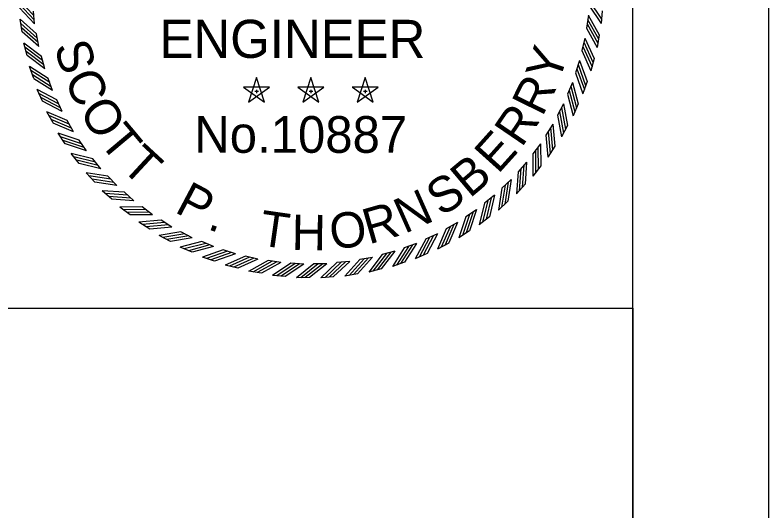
# Model space of a CAD drawing. Extents: x 0 to 1228740, y 0 to 152440.
# Drawn here: x 30.801 to 34, y 16.545 to 18.649 of the extents above; entities that cross this region are included whole.
import ezdxf

# ---------------------------------------------------------------- set-up
doc = ezdxf.new("R2010")
doc.units = 0
for name, color, linetype in [('R_Border', 7, 'Continuous'), ('R_No Plot', 7, 'Continuous'), ('STAMP_PP', 7, 'Continuous')]:
    doc.layers.add(name, color=color, linetype=linetype)

msp = doc.modelspace()

# ---------------------------------------------------------------- linework, layer by layer
at = {"layer": 'R_Border'}
msp.add_line((33.4231, 0.5768), (33.4231, 21.4232), dxfattribs=at)
msp.add_lwpolyline([(34, 22), (0, 22), (0, 0), (34, 0)], close=True, dxfattribs=at)
at = {"layer": 'R_No Plot'}
for points in [[(33.4231, 17.4052), (33.4231, 10.8708), (1.516, 10.8708), (1.516, 21.4232), (25.1971, 21.4232), (25.1971, 20.4352), (28.7491, 20.4352), (28.7491, 20.0782), (29.1131, 20.0782), (29.1131, 20.1432), (30.6665, 20.1432)], [(33.4231, 17.4052), (33.4231, 0.6568), (1.516, 0.6568), (1.516, 21.4232), (25.1971, 21.4232), (25.1971, 20.4352), (28.7491, 20.4352), (28.7491, 20.0782), (29.1131, 20.0782), (29.1131, 20.1432), (30.6665, 20.1432)], [(30.6665, 20.1432), (30.6665, 17.4052), (33.4231, 17.4052)], [(30.6665, 20.1432), (30.6665, 17.4052), (33.4231, 17.4052)]]:
    msp.add_lwpolyline(points, dxfattribs=at)
at = {"layer": 'STAMP_PP'}
for p, q in [((30.8837, 18.6117), (30.8787, 18.666)), ((33.2925, 18.6677), (33.2885, 18.6135)), ((30.8314, 18.5785), (30.822, 18.6321)), ((33.2337, 18.6484), (33.2252, 18.5945)), ((30.9013, 18.5154), (30.8918, 18.5691)), ((33.2793, 18.566), (33.2708, 18.5123)), ((30.8519, 18.478), (30.8381, 18.5306)), ((33.2191, 18.5516), (33.2062, 18.4986)), ((30.9268, 18.4209), (30.9129, 18.4737)), ((33.2577, 18.4657), (33.2449, 18.4129)), ((30.8807, 18.3796), (30.8626, 18.4309)), ((33.1965, 18.4563), (33.1793, 18.4046)), ((30.96, 18.3289), (30.9419, 18.3803)), ((31.8255, 18.384), (31.7915, 18.2795)), ((31.8594, 18.2796), (31.8256, 18.3841)), ((32.0563, 18.384), (32.0222, 18.2795)), ((32.0902, 18.2796), (32.0564, 18.3841)), ((32.2871, 18.384), (32.253, 18.2795)), ((32.321, 18.2796), (32.2871, 18.3841)), ((33.1662, 18.3633), (33.1447, 18.3131)), ((33.228, 18.3676), (33.2108, 18.316)), ((30.9175, 18.2838), (30.8952, 18.3335)), ((31.8804, 18.3441), (31.7705, 18.3442)), ((31.7706, 18.3441), (31.8594, 18.2795)), ((31.7916, 18.2796), (31.8805, 18.3441)), ((31.8256, 18.3324), (31.8256, 18.3186)), ((32.1112, 18.3441), (32.0013, 18.3442)), ((32.0014, 18.3441), (32.0902, 18.2795)), ((32.0224, 18.2796), (32.1113, 18.3441)), ((32.0564, 18.3324), (32.0564, 18.3186)), ((32.3419, 18.3441), (32.2321, 18.3442)), ((32.2322, 18.3441), (32.321, 18.2795)), ((32.2532, 18.2796), (32.3421, 18.3441)), ((32.2872, 18.3324), (32.2872, 18.3186)), ((31.8177, 18.3266), (31.834, 18.3266)), ((32.0485, 18.3266), (32.0648, 18.3266)), ((32.2793, 18.3266), (32.2956, 18.3266)), ((31.0007, 18.2399), (30.9784, 18.2896)), ((33.1283, 18.273), (33.1027, 18.2248)), ((33.1902, 18.2722), (33.1688, 18.2222)), ((30.9621, 18.1915), (30.9357, 18.2391)), ((31.0487, 18.1545), (31.0223, 18.2022)), ((33.083, 18.1863), (33.0536, 18.1403)), ((33.1447, 18.1803), (33.1192, 18.1323)), ((31.0141, 18.1031), (30.9839, 18.1484)), ((31.1035, 18.0734), (31.0732, 18.1188)), ((33.0308, 18.1035), (32.9977, 18.0601)), ((33.0917, 18.0925), (33.0624, 18.0467)), ((31.0733, 18.0193), (31.0395, 18.062)), ((31.1648, 17.9971), (31.1309, 18.0399)), ((32.9719, 18.0253), (32.9353, 17.9849)), ((31.1392, 17.9407), (31.1019, 17.9804)), ((33.0317, 18.0093), (32.9987, 17.9661)), ((31.2322, 17.9262), (31.1949, 17.966)), ((32.9067, 17.9523), (32.8669, 17.915)), ((32.965, 17.9314), (32.9286, 17.8911)), ((31.2113, 17.8678), (31.1709, 17.9043)), ((31.3052, 17.861), (31.2648, 17.8976)), ((32.8357, 17.8849), (32.793, 17.851)), ((32.8922, 17.8593), (32.8525, 17.8221)), ((31.2892, 17.8012), (31.246, 17.8342)), ((31.3834, 17.8021), (31.34, 17.8352)), ((32.7595, 17.8236), (32.7141, 17.7933)), ((32.8136, 17.7934), (32.7709, 17.7596)), ((31.3724, 17.7411), (31.3266, 17.7705)), ((31.4661, 17.7499), (31.4202, 17.7793)), ((32.6784, 17.7688), (32.6306, 17.7424)), ((31.5529, 17.7046), (31.5047, 17.7301)), ((32.7298, 17.7342), (32.6845, 17.704)), ((31.4602, 17.6882), (31.4121, 17.7136)), ((32.593, 17.7208), (32.5433, 17.6985)), ((31.5521, 17.6427), (31.5021, 17.6641)), ((31.6432, 17.6667), (31.593, 17.6882)), ((32.504, 17.6801), (32.4526, 17.662)), ((32.6414, 17.6822), (32.5938, 17.6558)), ((31.7362, 17.6364), (31.6845, 17.6536)), ((32.4119, 17.6469), (32.3592, 17.633)), ((32.549, 17.6376), (32.4994, 17.6153)), ((31.6475, 17.6049), (31.5959, 17.6221)), ((31.8315, 17.6138), (31.7785, 17.6267)), ((31.9283, 17.5992), (31.8744, 17.6077)), ((32.0259, 17.5927), (31.9715, 17.5967)), ((32.2212, 17.6038), (32.1669, 17.5988)), ((32.3175, 17.6214), (32.2637, 17.6119)), ((32.4533, 17.6008), (32.402, 17.5827)), ((31.7456, 17.5751), (31.6928, 17.588)), ((32.1238, 17.5942), (32.0692, 17.5937)), ((32.3549, 17.572), (32.3023, 17.5582)), ((31.8459, 17.5536), (31.7922, 17.5621)), ((31.9476, 17.5404), (31.8934, 17.5444)), ((32.0501, 17.5356), (31.9957, 17.5351)), ((32.1526, 17.5393), (32.0984, 17.5343)), ((32.2544, 17.5515), (32.2008, 17.5421))]:
    msp.add_line(p, q, dxfattribs=at)
for points in [[(30.8802, 18.6479), (30.8157, 18.7165)], [(30.8823, 18.6291), (30.8178, 18.6977)], [(33.2363, 18.6917), (33.2885, 18.6134)], [(33.2378, 18.7098), (33.29, 18.6315)], [(30.8838, 18.6117), (30.8193, 18.6803)], [(30.8918, 18.5691), (30.8219, 18.6321)], [(33.2307, 18.6312), (33.2764, 18.5488)], [(33.2336, 18.6484), (33.2793, 18.5661)], [(30.8948, 18.5512), (30.8249, 18.6142)], [(30.8985, 18.5327), (30.8286, 18.5957)], [(33.2252, 18.5945), (33.2709, 18.5122)], [(33.2282, 18.6124), (33.2739, 18.5301)], [(30.9014, 18.5154), (30.8315, 18.5784)], [(30.9129, 18.4736), (30.838, 18.5307)], [(33.2147, 18.5347), (33.2534, 18.4489)], [(33.219, 18.5517), (33.2577, 18.4658)], [(30.9174, 18.456), (30.8425, 18.5131)], [(30.9226, 18.4379), (30.8477, 18.4949)], [(33.2062, 18.4986), (33.2449, 18.4128)], [(33.2107, 18.5162), (33.2493, 18.4304)], [(30.9269, 18.4209), (30.852, 18.478)], [(30.9418, 18.3802), (30.8625, 18.4309)], [(33.1908, 18.4398), (33.2223, 18.3511)], [(33.1965, 18.4564), (33.228, 18.3677)], [(30.9477, 18.3631), (30.8684, 18.4138)], [(30.9544, 18.3454), (30.8751, 18.3961)], [(33.1793, 18.4046), (33.2108, 18.3159)], [(33.1852, 18.4218), (33.2167, 18.3331)], [(30.9601, 18.3288), (30.8808, 18.3795)], [(33.1662, 18.3634), (33.1902, 18.2723)], [(30.9784, 18.2895), (30.8951, 18.3335)], [(33.1591, 18.3473), (33.1832, 18.2563)], [(30.9857, 18.2729), (30.9024, 18.3169)], [(30.9938, 18.2559), (30.9105, 18.2998)], [(33.1448, 18.3132), (33.1688, 18.2222)], [(33.1521, 18.3298), (33.1761, 18.2388)], [(31.0008, 18.2398), (30.9176, 18.2838)], [(33.1282, 18.2731), (33.1447, 18.1804)], [(31.0223, 18.2022), (30.9357, 18.2391)], [(33.1114, 18.2408), (33.1279, 18.1481)], [(33.1199, 18.2577), (33.1364, 18.165)], [(31.0309, 18.1862), (30.9443, 18.2232)], [(31.0404, 18.1699), (30.9538, 18.2068)], [(33.1028, 18.2249), (33.1193, 18.1322)], [(31.0487, 18.1545), (30.9621, 18.1914)], [(33.0734, 18.1717), (33.0822, 18.0779)], [(33.083, 18.1863), (33.0917, 18.0926)], [(31.0732, 18.1187), (30.9839, 18.1484)], [(33.0537, 18.1404), (33.0624, 18.0466)], [(33.0636, 18.1555), (33.0723, 18.0618)], [(31.0831, 18.1036), (30.9938, 18.1332)], [(31.094, 18.0881), (31.0046, 18.1177)], [(31.1035, 18.0734), (31.0142, 18.1031)], [(33.02, 18.0898), (33.021, 17.9956)], [(33.0308, 18.1036), (33.0317, 18.0094)], [(31.1309, 18.0398), (31.0394, 18.062)], [(31.142, 18.0255), (31.0505, 18.0477)], [(32.9977, 18.0602), (32.9987, 17.966)], [(33.0089, 18.0745), (33.0098, 17.9803)], [(31.1541, 18.0109), (31.0626, 18.0331)], [(31.1649, 17.9971), (31.0734, 18.0193)], [(32.96, 18.0125), (32.9532, 17.9186)], [(32.9719, 18.0254), (32.9651, 17.9315)], [(31.1949, 17.9659), (31.1019, 17.9804)], [(32.9354, 17.9849), (32.9286, 17.891)], [(32.9477, 17.9982), (32.9408, 17.9043)], [(31.2072, 17.9526), (31.1142, 17.9671)], [(31.2204, 17.939), (31.1274, 17.9536)], [(32.9067, 17.9524), (32.8922, 17.8594)], [(31.2323, 17.9262), (31.1393, 17.9407)], [(32.8803, 17.9273), (32.8658, 17.8343)], [(32.8938, 17.9405), (32.8793, 17.8475)], [(31.2648, 17.8975), (31.1709, 17.9043)], [(31.2781, 17.8852), (31.1842, 17.8921)], [(32.8358, 17.885), (32.8136, 17.7935)], [(32.867, 17.915), (32.8525, 17.822)], [(31.2924, 17.8729), (31.1985, 17.8797)], [(31.3053, 17.861), (31.2114, 17.8678)], [(32.8074, 17.8621), (32.7852, 17.7706)], [(32.8219, 17.8742), (32.7998, 17.7827)], [(31.3401, 17.8351), (31.2459, 17.8342)], [(31.3544, 17.824), (31.2602, 17.8231)], [(32.7595, 17.8237), (32.7298, 17.7343)], [(32.7931, 17.851), (32.7709, 17.7595)], [(31.3696, 17.8129), (31.2755, 17.8119)], [(31.3835, 17.8021), (31.2893, 17.8012)], [(32.7142, 17.7933), (32.6845, 17.704)], [(32.7293, 17.8032), (32.6997, 17.7139)], [(32.7448, 17.8141), (32.7152, 17.7247)], [(31.4203, 17.7792), (31.3265, 17.7705)], [(31.4354, 17.7693), (31.3417, 17.7606)], [(31.4516, 17.7595), (31.3578, 17.7507)], [(32.663, 17.7605), (32.6261, 17.6739)], [(32.6784, 17.7688), (32.6415, 17.6823)], [(31.4662, 17.7499), (31.3725, 17.7411)], [(31.5048, 17.7301), (31.4121, 17.7136)], [(32.6307, 17.7424), (32.5938, 17.6558)], [(32.6467, 17.751), (32.6097, 17.6644)], [(31.5207, 17.7215), (31.428, 17.705)], [(31.5376, 17.713), (31.4449, 17.6965)], [(31.553, 17.7046), (31.4603, 17.6882)], [(32.5434, 17.6985), (32.4994, 17.6152)], [(32.56, 17.7058), (32.516, 17.6225)], [(32.577, 17.7139), (32.5331, 17.6306)], [(32.5931, 17.7209), (32.5491, 17.6377)], [(31.5931, 17.6881), (31.5021, 17.6641)], [(31.6097, 17.6808), (31.5187, 17.6568)], [(31.6272, 17.6738), (31.5362, 17.6497)], [(31.6433, 17.6667), (31.5522, 17.6427)], [(32.4527, 17.6619), (32.402, 17.5826)], [(32.4698, 17.6678), (32.4191, 17.5885)], [(32.4875, 17.6745), (32.4368, 17.5952)], [(32.5041, 17.6802), (32.4534, 17.6009)], [(31.6845, 17.6536), (31.5958, 17.6221)], [(31.7017, 17.6477), (31.613, 17.6162)], [(31.7197, 17.6421), (31.631, 17.6106)], [(31.7363, 17.6364), (31.6476, 17.6049)], [(32.3593, 17.633), (32.3022, 17.5581)], [(32.3768, 17.6375), (32.3198, 17.5626)], [(32.395, 17.6427), (32.338, 17.5678)], [(32.412, 17.647), (32.3549, 17.5721)], [(31.7785, 17.6267), (31.6927, 17.588)], [(31.7961, 17.6222), (31.7103, 17.5835)], [(31.8146, 17.6182), (31.7288, 17.5795)], [(31.8315, 17.6139), (31.7457, 17.5752)], [(31.8744, 17.6077), (31.7921, 17.562)], [(31.8923, 17.6047), (31.81, 17.559)], [(31.9111, 17.6022), (31.8287, 17.5565)], [(31.9283, 17.5993), (31.846, 17.5536)], [(31.9716, 17.5966), (31.8933, 17.5443)], [(32.1669, 17.5988), (32.0983, 17.5343)], [(32.185, 17.6003), (32.1164, 17.5358)], [(32.2038, 17.6024), (32.1352, 17.538)], [(32.2212, 17.6039), (32.1526, 17.5394)], [(32.2638, 17.6119), (32.2008, 17.542)], [(32.2817, 17.6149), (32.2186, 17.545)], [(32.3002, 17.6186), (32.2372, 17.5487)], [(32.3175, 17.6215), (32.2545, 17.5516)], [(31.9896, 17.5951), (31.9114, 17.5428)], [(32.0085, 17.5942), (31.9302, 17.5419)], [(32.026, 17.5927), (31.9477, 17.5404)], [(32.0693, 17.5937), (31.9956, 17.5351)], [(32.0874, 17.5937), (32.0137, 17.5351)], [(32.1063, 17.5943), (32.0326, 17.5357)], [(32.1238, 17.5943), (32.0501, 17.5357)]]:
    msp.add_lwpolyline(points, dxfattribs=at)

# ---------------------------------------------------------------- texts
for s, height, p in [('ENGINEER', 0.16155, (31.4137, 18.4677)), ('No.10887', 0.15578, (31.5614, 18.0649))]:
    msp.add_text(s, height=height, dxfattribs=at).set_placement(p)
for s, rotation, p in [('S', 286.9475, (30.9653, 18.5171)), ('Y', 71.7733, (33.1072, 18.3567)), ('C', 294.2435, (31.0071, 18.3799)), ('R', 63.7477, (33.0384, 18.2148)), ('O', 301.9044, (31.0694, 18.2429)), ('R', 55.7221, (32.9504, 18.084)), ('T', 309.93, (31.1536, 18.1096)), ('E', 48.0613, (32.8502, 17.9717)), ('T', 317.226, (31.2456, 17.9997)), ('B', 40.0357, (32.7301, 17.8695)), ('S', 32.7397, (32.6095, 17.7919)), ('P', 332.1828, (31.4737, 17.8153)), ('N', 23.9845, (32.4533, 17.72)), ('T', 351.882, (31.832, 17.6734)), ('R', 15.9589, (32.302, 17.6757)), ('H', 359.178, (31.974, 17.6531)), ('O', 7.9332, (32.146, 17.6529)), ('.', 340.2084, (31.6136, 17.7427))]:
    msp.add_text(s, height=0.1503, rotation=rotation, dxfattribs=at).set_placement(p)

doc.saveas('drawing.dxf')
